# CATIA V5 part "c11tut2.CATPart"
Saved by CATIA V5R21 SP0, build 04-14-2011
Part number: c11tut2
Bounding box of the stored display mesh (mm): x -175 to 0, y -36.667 to 105, z 0 to 36.632
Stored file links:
  D:\CATIA V5R21 E-RESOURCES\CATIA-V5R21\catia-v5r21-prt\c11-catia-v5r21-prt\c11-catia-v5r21-tut02.CATPart
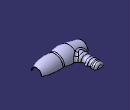
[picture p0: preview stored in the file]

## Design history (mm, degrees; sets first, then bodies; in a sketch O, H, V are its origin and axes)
Body1 (main body)
  Plane1: type Offset, RefPlane yz-plane, Offset 75, reversed
  Plane2: type Offset, RefPlane yz-plane, Offset 125, reversed
  Plane3: type Offset, RefPlane yz-plane, Offset 175, reversed
  Sketch1 on yz-plane, origin (0, 0, 0), H (0, 1, 0), V (0, 0, 1)
    arc A1 centre (0, 0) radius 20 from (20, 0) to (-20, 0) ccw
    point P1 (-20, 0)
    point P2 (20, 0)
    radius A1 = 20
    coincidence: P1 H, P2 H
  Sketch2 on Plane1, origin (-75, 0, 0), H (0, 1, 0), V (0, 0, 1)
    arc A1 centre (0, 0) radius 30 from (30, 0) to (-30, 0) ccw
    point P1 (-30, 0)
    point P2 (30, 0)
    radius A1 = 30
    coincidence: P1 H, P2 H
  Sketch3 on Plane2, origin (-125, 0, 0), H (0, 1, 0), V (0, 0, 1)
    arc A1 centre (0, 0) radius 35 from (35, 0) to (-35, 0) ccw
    point P1 (-35, 0)
    point P2 (35, 0)
    radius A1 = 35
    coincidence: P1 H, P2 H
  Sketch4 on Plane3, origin (-175, 0, 0), H (0, 1, 0), V (0, 0, 1)
    arc A1 centre (0, 0) radius 25 from (25, 0) to (-25, 0) ccw
    point P1 (-25, 0)
    point P2 (25, 0)
    radius A1 = 25
    coincidence: P1 H, P2 H
  Sketch5 on xy-plane, origin (0, 0, 0), H (1, 0, 0), V (0, 1, 0)
    arc A1 centre (-53.2457, -93.0924) radius 125 from (0, 20) to (-75, 30) ccw
    point P2 (0, 20)
    point P3 (-75, 30)
    reference projected point E1 (0, 20) from Sketch1.P2
    reference projected point E2 (-75, 30) from Sketch2.P2
    line L1 (-175, 25) -> (-125, 35)
    point P4 (-175, 25)
    point P5 (-125, 35)
    reference projected point E3 (-125, 35) from Sketch3.P2
    reference projected point E4 (-175, 25) from Sketch4.P2
    arc A2 centre (-108.1667, -49.1667) radius 85.8335 from (-75, 30) to (-125, 35) ccw
    radius A1 = 125
    coincidence: P2 V, P2 E1, P3 E2, P5 E3, E4 P4
    tangency: A2 L1
  Sketch6 on xy-plane, origin (0, 0, 0), H (1, 0, 0), V (0, 1, 0)
    reference projected line E1 (-125, 35) -> (-175, 25) from Sketch5.L1
    point P1 (-125, 35)
    point P2 (-175, 25)
    reference projected arc E2 centre (-108.1667, -49.1667) radius 85.8335 from (-75, 30) to (-125, 35) ccw from Sketch5.A2
    point P3 (-75, 30)
    point P4 (-125, 35)
    reference projected arc E3 centre (-53.2457, -93.0924) radius 125 from (0, 20) to (-75, 30) ccw from Sketch5.A1
    point P5 (0, 20)
    point P6 (-75, 30)
    point P7 (-75, -30)
    point P8 (0, -20)
    point P9 (-125, -35)
    point P10 (-75, -30)
    point P11 (-175, -25)
    point P12 (-125, -35)
    arc A1 centre (-53.2457, 93.0924) radius 125 from (0, -20) to (-75, -30) cw
    arc A2 centre (-108.1667, 49.1667) radius 85.8335 from (-75, -30) to (-125, -35) cw
    line L1 (-125, -35) -> (-175, -25)
    symmetry: P6 P7 H, P5 P8 H, E3 A1 H, P4 P9 H, P3 P10 H, E2 A2 H, P2 P11 H, P1 P12 H, E1 L1 H
  Loft1: Sections (Sketch1; Sketch2; Sketch3; Sketch4), Guides (Sketch5; Sketch6)
  Sketch7 on xy-plane, origin (0, 0, 0), H (1, 0, 0), V (0, 1, 0)
    line L1 (-160, 10) -> (-160, 105)
    point P1 (-160, 10)
    point P2 (-160, 105)
    reference projected line E1 (-175, -25) -> (-175, 25) from edge of Loft1
    reference projected point E2 (-175, 25) from vertex [face of Loft1]
    distance P1 E1 = 15
    distance E2 P1 V = 15
    distance H P2 = 105
    vertical: L1 V
  Sketch8 on xy-plane, origin (0, 0, 0), H (1, 0, 0), V (0, 1, 0)
    point P1 (-125, 105)
    construction line L1 (-125, 105) -> (-110.3491, 0.7536)
    line L2 (-125, 105) -> (-123.011, 90.8478)
    point P3 (-123.011, 90.8478)
    arc A1 centre (-129.9429, 89.8736) radius 7 from (-125.3895, 84.5571) to (-123.011, 90.8478) ccw
    point P5 (-123.011, 90.8478)
    arc A2 centre (-121.4865, 80) radius 6 from (-125.3895, 84.5571) to (-123.3627, 74.3009) ccw
    point P7 (-121.4865, 80)
    arc A3 centre (-124.8481, 69.7891) radius 4.75 from (-122.6028, 65.6033) to (-123.3627, 74.3009) ccw
    arc A4 centre (-118.3485, 57.6723) radius 9 from (-122.6028, 65.6033) to (-122.4134, 49.6426) ccw
    point P11 (-118.3485, 57.6723)
    arc A5 centre (-127.8333, 38.9362) radius 12 from (-115.9501, 40.6063) to (-122.4134, 49.6426) ccw
    construction line L3 (-160, 10) -> (-111.6486, 10)
    point P15 (-160, 10)
    line L4 (-111.6486, 10) -> (-115.9501, 40.6063)
    reference projected point E1 (-160, 10) from Sketch7.P1
    construction line L5 (-160, 105) -> (-125, 105)
    point P17 (-160, 105)
    point P18 (-125, 105)
    reference projected point E2 (-160, 105) from Sketch7.P2
    radius A1 = 7
    radius A2 = 6
    radius A3 = 4.75
    radius A4 = 9
    radius A5 = 12
    length L5 = 35
    distance P7 L5 = 25
    angle L5 L1 = 98
    parallelism: L2 L1
    tangency: A1 L1, A2 A1, A2 A3, A3 L1, A4 A3, A5 A4, L4 A5
    coincidence: P5 L1, P5 P3, P7 L1, P11 L1, P15 E1, P17 E2, P1 P18, L1 L4
    horizontal: L3 H, L5 H
  Plane4: type Offset, RefPlane zx-plane, Offset 105
  Sketch9 on Plane4, origin (0, 105, 0), H (-1, 0, 0), V (0, 0, 1)
    arc A1 centre (142.5, 0) radius 17.5 from (160, 0) to (125, 0) ccw
    point P2 (160, 0)
    point P3 (125, 0)
    reference projected point E1 (125, 0) from Sketch8.P1
    reference projected point E2 (160, 0) from Sketch7.P2
    radius A1 = 17.5
    coincidence: P3 E1, P2 E2
  Sweep1: type Unspec, Profile Sketch9, Guide (Sketch7; Sketch8), FittingPoints (Sketch7.P2; Sketch8.P1)
  Trim1: Trimmed (Sweep1; Loft1)
  Line1: type PtPt, FirstPoint vertex [face of Loft1], SecondPoint vertex [face of Loft1]
  Fill1: Boundary (edge of Loft1; Line1)
  Line2: type PtPt, FirstPoint vertex [face of Sweep1], SecondPoint vertex [face of Sweep1]
  Fill2: Boundary (edge of Sweep1; Line2)
  Line3: type PtPt, FirstPoint vertex [face of Loft1], SecondPoint vertex [face of Loft1]
  Fill3: Boundary (Line3; edge of Loft1)
  Fill4: Boundary (edge of Sweep1; edge of Sweep1; edge of Sweep1; edge of Sweep1; edge of Sweep1; edge of Sweep1; edge of Sweep1; Line2; edge of Sweep1; edge of Loft1; Line3; edge of Loft1; edge of Loft1; edge of Loft1; Line1; edge of Loft1; edge of Loft1)
  Join1: Elements (Fill4; Fill3; Trim1; Fill1; Fill2)
  CloseSurface1: CloseElement Join1
  Fillet1: radius 8, on edge [face of CloseSurface1 | face of CloseSurface1]
  Fillet2: radius 12, on edge [face of CloseSurface1 | face of CloseSurface1] (x2)
  Shell1: ExtOffset 0, Face (face of CloseSurface1; face of CloseSurface1; face of CloseSurface1), IntOffset 1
